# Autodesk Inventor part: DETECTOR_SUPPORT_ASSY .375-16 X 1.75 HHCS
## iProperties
Shininess: 64.0
Length Units: 11272
Angle Units: 11279
Time Units: 11290
Mass Units: 11286
Length Display Precision: 3
Angle Display Precision: 2
Compacted: True
Part Number: DETECTOR_SUPPORT_ASSY .375-16 X 1.75 HHCS
Document SubType Name: Modeling
Created: 2004-08
Designer: John Blackburn
Material: STAINLESS_STEEL, AUSTENITIC
Manufacturer: Standard
Standards Organization: Custom
Density: 0.0
Volumn: 0.0
Area: 0.0
PropertySet Name: Model Information
Control State: 0
Master: False
Checked Out: False
Author: John Blackburn
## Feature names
1. Base1
